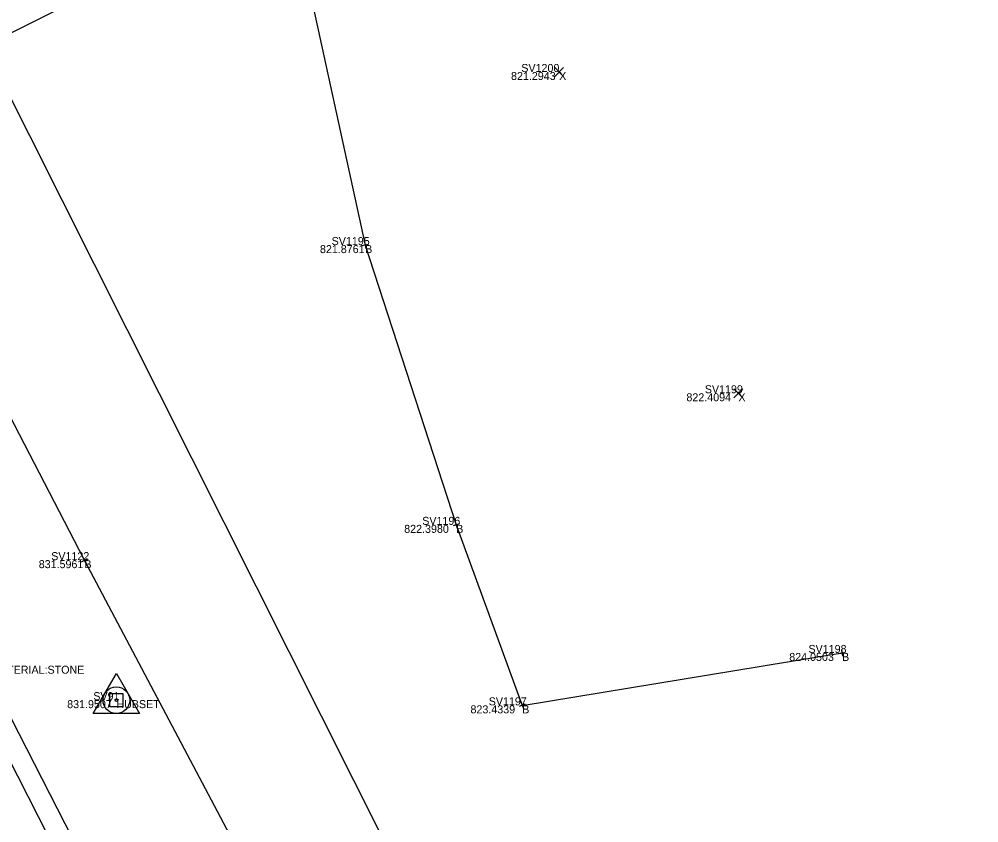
# Model space of a CAD drawing. Extents: x 1715717 to 1717046, y 393954 to 396000.
# Drawn here: x 1716099.6 to 1716171.5, y 394998.7 to 395058.9 of the extents above; entities that cross this region are included whole.
import ezdxf

# ---------------------------------------------------------------- set-up
doc = ezdxf.new("R2010")
doc.units = 0
for name, color, linetype in [('DR_X_Storm_Sewer', 7, 'Continuous'), ('PV_X_EOP', 7, 'Continuous'), ('PV_X_Shoulder', 7, 'Continuous'), ('SV_Control_Point', 7, 'Continuous'), ('SV_P_Control_Cells_Set', 7, 'Continuous'), ('SV_X_Break_Lines', 7, 'Continuous'), ('SV_X_Random_Point', 7, 'Continuous'), ('SV_X_Shot_Marker', 7, 'Continuous'), ('SV_X_Text_Comment', 7, 'Continuous'), ('SV_X_Text_Description', 7, 'Continuous'), ('SV_X_Text_Elevation', 7, 'Continuous'), ('SV_X_Text_Name', 7, 'Continuous'), ('UT_X_Overhead_Electric', 7, 'Continuous')]:
    doc.layers.add(name, color=color, linetype=linetype)

msp = doc.modelspace()

# ---------------------------------------------------------------- linework, layer by layer
at = {"layer": 'DR_X_Storm_Sewer'}
msp.add_lwpolyline([(1716018.945, 395025.216), (1716021.933, 395019.264), (1716112.327, 395064.643), (1716109.339, 395070.595)], close=True, dxfattribs=at)
at = {"layer": 'PV_X_EOP'}
msp.add_lwpolyline([(1715929.814, 395331.503), (1715942.058, 395307.246), (1715954.628, 395282.99), (1715967.171, 395258.584), (1715979.735, 395234.334), (1715992.41, 395210.155), (1716005.047, 395185.868), (1716017.244, 395162.112), (1716029.552, 395138.177), (1716042.205, 395113.852), (1716053.65, 395091.043), (1716066.067, 395067.091), (1716078.295, 395043.082), (1716090.961, 395018.84), (1716103.285, 394994.646), (1716114.625, 394973.14), (1716128.545, 394946.999), (1716142.053, 394921.754), (1716156.217, 394894.569), (1716168.55, 394869.122), (1716181.54, 394844.329), (1716193.516, 394820.028), (1716205.073, 394797.305), (1716213.118, 394780.996)], dxfattribs=at)
at = {"layer": 'PV_X_Shoulder'}
msp.add_lwpolyline([(1716218.792, 394784.257), (1716209.02, 394803.209), (1716198.261, 394826.709), (1716187.193, 394850.774), (1716177.584, 394869.878), (1716164.307, 394888.931), (1716155.098, 394901.616), (1716142.963, 394923.855), (1716131.691, 394943.842), (1716122.734, 394959.891), (1716109.899, 394985.171), (1716097.238, 395009.873), (1716085.103, 395034.541), (1716073.079, 395057.728), (1716060.799, 395082.423), (1716047.789, 395108.139), (1716034.623, 395132.606), (1716021.86, 395157.298), (1716009.498, 395181.108), (1715996.317, 395206.486), (1715983.132, 395232.342), (1715969.299, 395258.699)], dxfattribs=at)
at = {"layer": 'SV_Control_Point'}
for p, q in [((1716105.126, 395006.892), (1716106.858, 395009.892)), ((1716106.858, 395009.892), (1716108.59, 395006.892)), ((1716106.858, 395007.892), (1716106.858, 395007.892)), ((1716108.59, 395006.892), (1716105.126, 395006.892))]:
    msp.add_line(p, q, dxfattribs=at)
msp.add_circle((1716106.858, 395007.892), 1, dxfattribs=at)
at = {"layer": 'SV_P_Control_Cells_Set'}
msp.add_lwpolyline([(1716106.363, 395008.388), (1716107.353, 395008.388), (1716107.353, 395007.397), (1716106.363, 395007.397), (1716106.363, 395008.388)], dxfattribs=at)
msp.add_circle((1716106.858, 395007.892), 0.1, dxfattribs=at)
at = {"layer": 'SV_X_Break_Lines'}
for points in [[(1716158.601, 394970.074), (1716139.797, 394971.592), (1716129.375, 394977.66), (1716116.262, 394996.103), (1716104.461, 395018.386), (1716092.441, 395041.581), (1716080.607, 395065.634), (1716068.81, 395086.953), (1716057.337, 395108.575), (1716045.341, 395131.286), (1716034.093, 395153.59), (1716023.737, 395175.943), (1716017.203, 395192.883), (1716015.802, 395192.717)], [(1716121.345, 395061.139), (1716125.515, 395042.004), (1716132.348, 395021.032), (1716137.296, 395007.501), (1716161.282, 395011.431)]]:
    msp.add_lwpolyline(points, dxfattribs=at)
at = {"layer": 'SV_X_Random_Point'}
for p, q in [((1716139.733, 395054.647), (1716140.399, 395055.314)), ((1716139.733, 395055.314), (1716140.399, 395054.647)), ((1716153.175, 395030.564), (1716153.842, 395031.231)), ((1716153.175, 395031.231), (1716153.842, 395030.564))]:
    msp.add_line(p, q, dxfattribs=at)
at = {"layer": 'SV_X_Shot_Marker'}
for p, q in [((1716125.759, 395042.058), (1716125.271, 395041.951)), ((1716125.462, 395042.249), (1716125.568, 395041.76)), ((1716125.515, 395042.004), (1716125.515, 395042.004)), ((1716132.586, 395021.11), (1716132.11, 395020.955)), ((1716132.27, 395021.27), (1716132.425, 395020.795)), ((1716132.348, 395021.032), (1716132.348, 395021.032)), ((1716104.24, 395018.269), (1716104.682, 395018.503)), ((1716104.578, 395018.165), (1716104.344, 395018.607)), ((1716104.461, 395018.386), (1716104.461, 395018.386)), ((1716161.035, 395011.391), (1716161.528, 395011.472)), ((1716161.241, 395011.678), (1716161.322, 395011.184)), ((1716161.282, 395011.431), (1716161.282, 395011.431)), ((1716137.53, 395007.587), (1716137.061, 395007.415)), ((1716137.21, 395007.735), (1716137.381, 395007.266)), ((1716137.296, 395007.501), (1716137.296, 395007.501))]:
    msp.add_line(p, q, dxfattribs=at)
at = {"layer": 'UT_X_Overhead_Electric'}
msp.add_line((1716142.676, 394966.115), (1715910.386, 395427.624), dxfattribs=at)

# ---------------------------------------------------------------- texts
at = {"layer": 'SV_X_Text_Comment'}
for s, p in [('X', (1716140.066, 395054.38)), ('B', (1716125.515, 395041.404)), ('X', (1716153.509, 395030.297)), ('B', (1716132.348, 395020.432)), ('B', (1716104.461, 395017.786)), ('B', (1716161.282, 395010.831)), ('HUBSET', (1716106.858, 395007.292)), ('B', (1716137.296, 395006.901))]:
    msp.add_text(s, height=0.6, dxfattribs=at).set_placement(p)
at = {"layer": 'SV_X_Text_Description'}
msp.add_text(' MATERIAL:STONE ', height=0.6, dxfattribs=at).set_placement((1716097.238, 395009.873))
at = {"layer": 'SV_X_Text_Elevation'}
for s, p in [('821.2943', (1716136.457, 395054.38)), ('821.8761', (1716122.128, 395041.404)), ('822.4094', (1716149.611, 395030.297)), ('822.3980', (1716128.446, 395020.432)), ('831.5961', (1716101.037, 395017.786)), ('824.0503', (1716157.323, 395010.831)), ('831.9507', (1716103.169, 395007.292)), ('823.4339', (1716133.417, 395006.901))]:
    msp.add_text(s, height=0.6, dxfattribs=at).set_placement(p)
at = {"layer": 'SV_X_Text_Name'}
for s, p in [('SV1200', (1716137.227, 395054.98)), ('SV1195', (1716123.002, 395042.004)), ('SV1199', (1716150.991, 395030.897)), ('SV1196', (1716129.797, 395021.032)), ('SV1122', (1716101.972, 395018.386)), ('SV1198', (1716158.764, 395011.431)), ('SV91', (1716105.129, 395007.892)), ('SV1197', (1716134.783, 395007.501))]:
    msp.add_text(s, height=0.6, dxfattribs=at).set_placement(p)

doc.saveas('drawing.dxf')
